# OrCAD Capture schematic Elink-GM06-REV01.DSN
size A2; title: Elink-GM06-REV01; note: Power-Tree
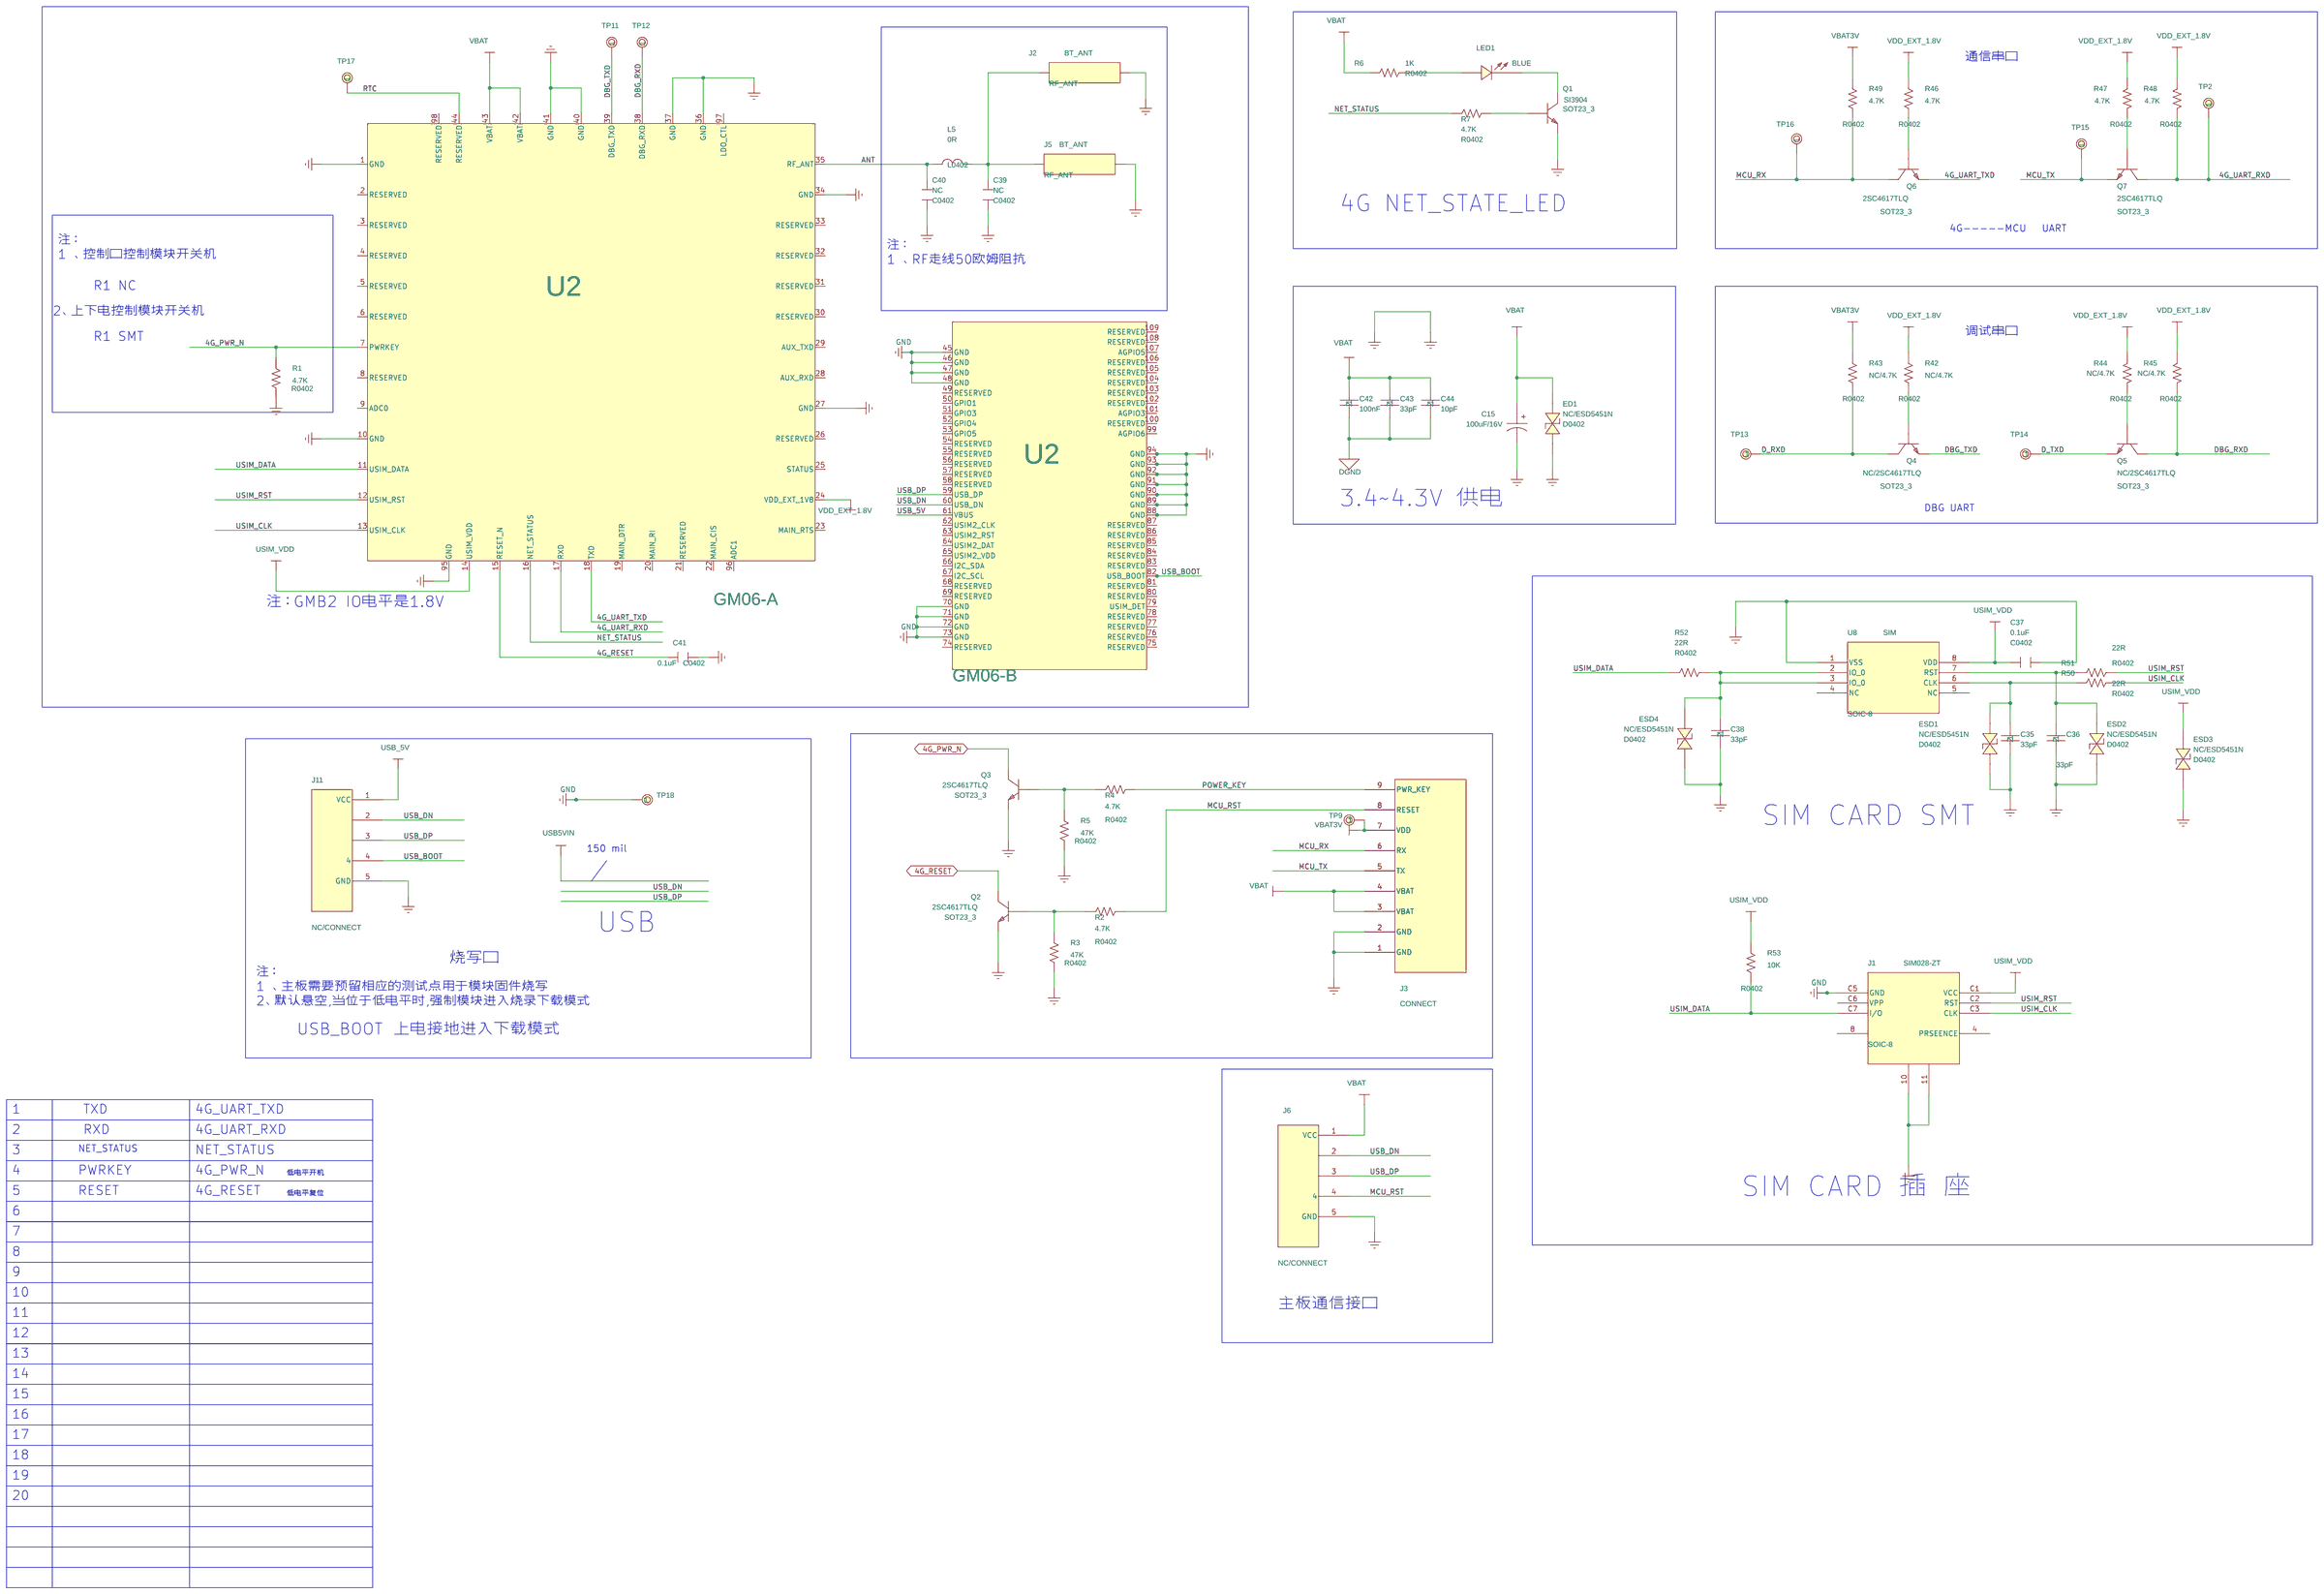
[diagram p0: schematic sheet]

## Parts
C15  100uF/16V
C35  33pF  [0402m]
C36  33pF  [0402m]
C37  0.1uF  [C0402]
C38  33pF  [0402m]
C39  NC  [C0402]
C40  NC  [C0402]
C41  0.1uF  [C0402]
C42  100nF  [0402m]
C43  33pF  [0402m]
C44  10pF  [0402m]
ED1  NC/ESD5451N  [D0402]
ESD1  NC/ESD5451N  [D0402]
ESD2  NC/ESD5451N  [D0402]
ESD3  NC/ESD5451N  [D0402]
ESD4  NC/ESD5451N  [D0402]
J1  SIM028-ZT  [SOIC-8]
J2  BT_ANT  [RF_ANT]
J3  CONNECT  [MICROUSB-180-5P]
J5  BT_ANT  [RF_ANT]
J6  NC/CONNECT  [MICROUSB-180-5P]
J11  NC/CONNECT  [MICROUSB-180-5P]
L5  0R  [L0402]
LED1  BLUE  [LED0603A]
Q1  SI3904  [SOT23_3]
Q2  2SC4617TLQ  [SOT23_3]
Q3  2SC4617TLQ  [SOT23_3]
Q4  NC/2SC4617TLQ  [SOT23_3]
Q5  NC/2SC4617TLQ  [SOT23_3]
Q6  2SC4617TLQ  [SOT23_3]
Q7  2SC4617TLQ  [SOT23_3]
R1  4.7K  [R0402]
R2  4.7K  [R0402]
R3  47K  [R0402]
R4  4.7K  [R0402]
R5  47K  [R0402]
R6  1K  [R0402]
R7  4.7K  [R0402]
R42  NC/4.7K  [R0402]
R43  NC/4.7K  [R0402]
R44  NC/4.7K  [R0402]
R45  NC/4.7K  [R0402]
R46  4.7K  [R0402]
R47  4.7K  [R0402]
R48  4.7K  [R0402]
R49  4.7K  [R0402]
R50  22R  [R0402]
R51  22R  [R0402]
R52  22R  [R0402]
R53  10K  [R0402]
TP2  TP  [TP50]
TP9  TP  [TP50]
TP11  TP  [TP50]
TP12  TP  [TP50]
TP13  TP  [TP50]
TP14  TP  [TP50]
TP15  TP  [TP50]
TP16  TP  [TP50]
TP17  TP  [TP50]
TP18  TP  [TP50]
U2  GM06-B  [aQFN60mp]
U8  SIM  [SOIC-8]

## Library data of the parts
C15 = CAPACITOR_POL_0
C35 = AVX_.01_uF_0603_4
C36 = AVX_.01_uF_0603_3
C37 = CAPACITOR_1: PAGE: 1
C38 = AVX_.01_uF_0603_2
C39-C41 = CAPACITOR_0: PAGE: 1
C42 = AVX_.01_uF_0603_5
C43 = AVX_.01_uF_0603
C44 = AVX_.01_uF_0603_1
ED1 ESD1-ESD4 = 1_1.5KE100A: 1ST PART DESCRIPTION: WILL ESD9B5V Bidirection ESD Protection
J1 = BMA222_25
J2 J5 = FM_ANT_7
J3 = MINIUSB_17
J6 J11 = MINIUSB_13
L5 = INDUCTOR_2
LED1 = LED
Q1-Q7 = NPN_BEC
R1-R7 R42-R53 = R_v3
TP2 TP9 TP11-TP18 = TEST_POINT_SMD0.6: Test Pad; Unit Price: 0
U2 = DA14680_aQFN_7
U8 = BMA222_1

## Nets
DGND: C42.2 C43.2 C44.2
VBAT: C15.1 C42.1 C43.1 C44.1 ED1.2(CATHODE) J3.3(VBAT) J3.4(VBAT) J6.1(VCC) R6.2 U2.42(VBAT) U2.43(VBAT)
VBAT3V: J3.7(VDD) R43.1 R49.1 TP9.1
VDD_EXT_1.8V: R42.1 R44.1 R45.1 R46.1 R47.1 R48.1 U2.24(VDD_EXT_1V8)
4G_PWR_N: Q3.3(C) R1.1 U2.7(PWRKEY)
4G_RESET: C41.2 Q2.3(C) U2.15(RESET_N)
4G_UART_RXD: Q7.3(C) R48.2 TP2.1 U2.17(RXD)
4G_UART_TXD: Q6.2(E) U2.18(TXD)
ADC1: U2.96(ADC1)
ANT: C40.2 L5.1 U2.35(RF_ANT)
D_RXD: Q4.3(C) R43.2 TP13.1
D_TXD: Q5.2(E) TP14.1
DBG_RXD: Q5.3(C) R45.2 TP12.1 U2.38(DBG_RXD)
DBG_TXD: Q4.2(E) TP11.1 U2.39(DBG_TXD)
GGND: C15.2 C35.2 C36.2 C37.2 C38.2 C39.1 C40.1 C41.1 ED1.1(ANODE) ESD1.1(ANODE) ESD2.1(ANODE) ESD3.1(ANODE) ESD4.1(ANODE) J1.10 J1.11 J1.C5(GND) J2.2 J3.1(GND) J3.2(GND) J5.2 J6.5(GND) J11.5(GND) Q1.2(E) Q2.2(E) Q3.2(E) R1.2 R3.2 R5.2 TP18.1 U2.1(GND) U2.10(GND) U2.27(GND) U2.34(GND) U2.36(GND) U2.37(GND) U2.40(GND) U2.41(GND) U2.45(GND) U2.46(GND) U2.47(GND) U2.48(GND) U2.70(GND) U2.71(GND) U2.72(GND) U2.73(GND) U2.88(GND) U2.89(GND) U2.90(GND) U2.91(GND) U2.92(GND) U2.93(GND) U2.94(GND) U2.95(GND) U8.1(VSS)
LDO_CTL: U2.97(LDO_CTL)
MAIN_CIS: U2.22(MAIN_CIS)
MAIN_DTR: U2.19(MAIN_DTR)
MAIN_RI: U2.20(MAIN_RI)
MCU_RST: J3.8(RESET) J6.4 R2.2
MCU_RX: J3.6(RX) Q6.3(C) R49.2 TP16.1
MCU_TX: J3.5(TX) Q7.2(E) TP15.1
NET_STATUS: R7.1 U2.16(NET_STATUS)
POWER_KEY: J3.9(PWR_KEY) R4.2
RESERVED: U2.21(RESERVED) U2.98(RESERVED)
RTC: TP17.1 U2.44(RESERVED)
USB_5V: J11.1(VCC) U2.61(VBUS)
USB_BOOT: J11.4 U2.82(USB_BOOT)
USB_DN: J6.2 J11.2 U2.60(USB_DN)
USB_DP: J6.3 J11.3 U2.59(USB_DP)
USIM_CLK: J1.C3(CLK) R50.1 U2.13(USIM_CLK)
USIM_DATA: J1.C7(I/O) R52.2 R53.2 U2.11(USIM_DATA)
USIM_RST: J1.C2(RST) R51.1 U2.12(USIM_RST)
USIM_VDD: C37.1 ESD3.2(CATHODE) J1.C1(VCC) R53.1 U2.14(USIM_VDD) U8.8(VDD)
N29521520: C39.2 J2.1 J5.1 L5.2
N29581955: LED1.1(CATHODE) Q1.3(C)
N29581959: Q1.1(B) R7.2
N29581966: LED1.2(ANODE) R6.1
N29588258: Q6.1(B) R46.2
N29588274: Q7.1(B) R47.2
N29588503: Q4.1(B) R42.2
N29588522: Q5.1(B) R44.2
N29588847: Q2.1(B) R2.1 R3.1
N29588901: Q3.1(B) R4.1 R5.1
N29590256: C36.1 ESD2.2(CATHODE) R51.2 U8.7(RST)
N29590258: C35.1 ESD1.2(CATHODE) R50.2 U8.6(CLK)
N29590260: C38.1 ESD4.2(CATHODE) R52.1 U8.2(IO_0) U8.3(IO_0)

Not connected (* = marked no-connect by the designer): J1 4(PRSEENCE) 8 C6(VPP); U2 2(RESERVED) 3(RESERVED) 4(RESERVED) 5(RESERVED) 6(RESERVED) 8(RESERVED) 9(ADC0) 23(MAIN_RTS) 25(STATUS) 26(RESERVED) 28(AUX_RXD) 29(AUX_TXD) 30(RESERVED) 31(RESERVED) 32(RESERVED) 33(RESERVED) 49(RESERVED) 50(GPIO1) 51(GPIO3) 52(GPIO4) 53(GPIO5) 54(RESERVED) 55(RESERVED) 56(RESERVED) 57(RESERVED) 58(RESERVED) 62(USIM2_CLK) 63(USIM2_RST) 64(USIM2_DAT) 65(USIM2_VDD) 66(I2C_SDA) 67(I2C_SCL) 68(RESERVED) 69(RESERVED) 74(RESERVED) 75(RESERVED) 76(RESERVED) 77(RESERVED) 78(RESERVED) 79(USIM_DET) 80(RESERVED) 81(RESERVED) 83(RESERVED) 84(RESERVED) 85(RESERVED) 86(RESERVED) 87(RESERVED) 99(AGPIO6) 100(RESERVED) 101(AGPIO3) 102(RESERVED) 103(RESERVED) 104(RESERVED) 105(RESERVED) 106(RESERVED) 107(AGPIO5) 108(RESERVED) 109(RESERVED); U8 4(NC) 5(NC)

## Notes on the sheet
- 通信串口
- 4G NET_STATE_LED
- 注：
  1 、控制口控制模块开关机
- 4G-----MCU   UART
- 注：
  1 、RF走线50欧姆阻抗
- R1 NC
- 2、上下电控制模块开关机
- R1 SMT
- 调试串口
- 3.4~4.3V 供电
- DBG UART
- 注：GMB2 IO电平是1.8V
- SIM CARD SMT
- 150 mil
- USB
- 烧写口
- 注：
  1 、主板需要预留相应的测试点用于模块固件烧写
  2、默认悬空,当位于低电平时,强制模块进入烧录下载模式
- USB_BOOT
- 上电接地进入下载模式
- 1
- TXD
- 4G_UART_TXD
- 2
- RXD
- 4G_UART_RXD
- 3
- NET_STATUS
- NET_STATUS
- 4
- PWRKEY
- 4G_PWR_N
- 低电平开机
- SIM CARD 插 座
- 5
- RESET
- 4G_RESET
- 低电平复位
- 6
- 7
- 8
- 9
- 10
- 主板通信接口
- 11
- 12
- 13
- 14
- 15
- 16
- 17
- 18
- 19
- 20
